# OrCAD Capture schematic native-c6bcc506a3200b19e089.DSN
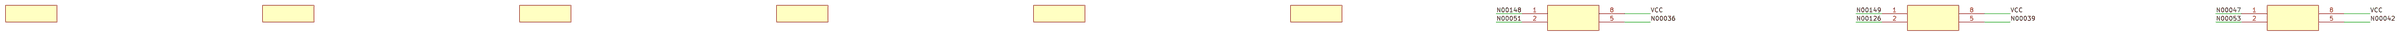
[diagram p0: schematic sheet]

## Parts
R1  100K1
R2  470K1
R4  100K1
R5  1470K1
R7  100K1
R8  470K1
U1  UNKNOWN
U2  UNKNOWN
U3  UNKNOWN

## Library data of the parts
R1 = OBS_R1
R2 = OBS_R2
R4 = OBS_R4
R5 = OBS_R5
R7 = OBS_R7
R8 = OBS_R8
U1 = OBS_U1
U2 = OBS_U2
U3 = OBS_U3

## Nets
VCC: U1.8 U2.8 U3.8

Not connected (* = marked no-connect by the designer): U1 1 2 5; U2 1 2 5; U3 1 2 5
